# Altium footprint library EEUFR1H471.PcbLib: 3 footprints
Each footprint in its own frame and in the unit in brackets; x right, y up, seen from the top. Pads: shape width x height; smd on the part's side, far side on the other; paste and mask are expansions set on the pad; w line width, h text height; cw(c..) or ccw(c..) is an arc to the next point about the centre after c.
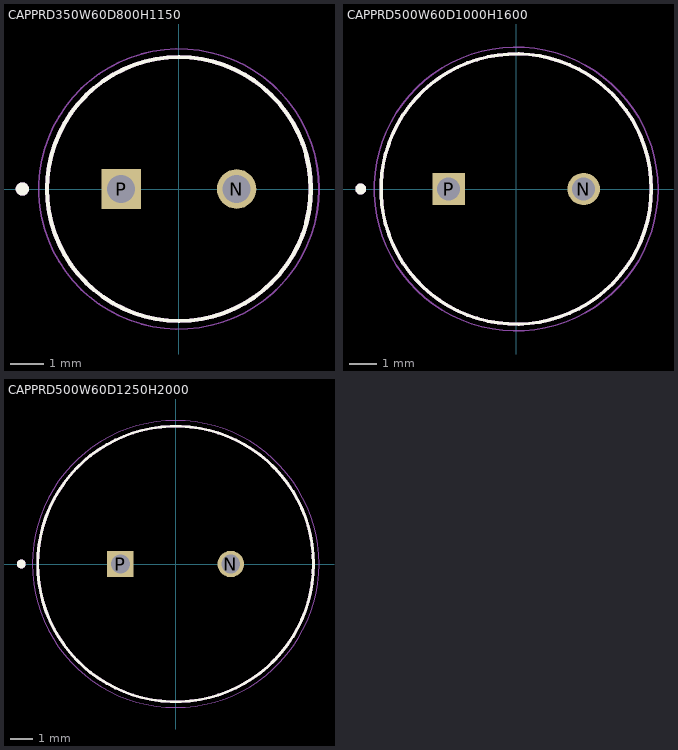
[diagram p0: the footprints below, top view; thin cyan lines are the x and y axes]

## CAPPRD350W60D800H1150 [mm]
pads (2):
  round 1.2 hole 0.85: N(1.75,0)
  rect 1.2x1.2 hole 0.85: P(-1.75,0)
Top Overlay:
  circle w0.127: c0,0 r4
  circle w0.2: c-4.75,0 r0.1
Mechanical 13:
  circle w0.127: c0,0 r4
  circle w0.2: c-4.75,0 r0.1
Mechanical 15:
  circle w0.05: c0,0 r4.25
3D body "step_temp.STEP": height 11.5, standoff -17, extent -4,-4 4,4

## CAPPRD500W60D1000H1600 [mm]
pads (2):
  round 1.2 hole 0.85: N(2.5,0)
  rect 1.2x1.2 hole 0.85: P(-2.5,0)
Top Overlay:
  circle w0.127: c0,0 r5
  circle w0.2: c-5.75,0 r0.1
Mechanical 13:
  circle w0.127: c0,0 r5
  circle w0.2: c-5.75,0 r0.1
Mechanical 15:
  circle w0.05: c0,0 r5.25
3D body "step_temp.STEP": height 16, standoff -17, extent -5,-4.999 5,4.999

## CAPPRD500W60D1250H2000 [mm]
pads (2):
  round 1.2 hole 0.85: N(2.5,0)
  rect 1.2x1.2 hole 0.85: P(-2.5,0)
Top Overlay:
  circle w0.127: c0,0 r6.25
  circle w0.2: c-7,0 r0.1
Mechanical 13:
  circle w0.127: c0,0 r6.25
  circle w0.2: c-7,0 r0.1
Mechanical 15:
  circle w0.05: c0,0 r6.5
3D body "step_temp.STEP": height 20, standoff -17, extent -6.25,-6.249 6.25,6.249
